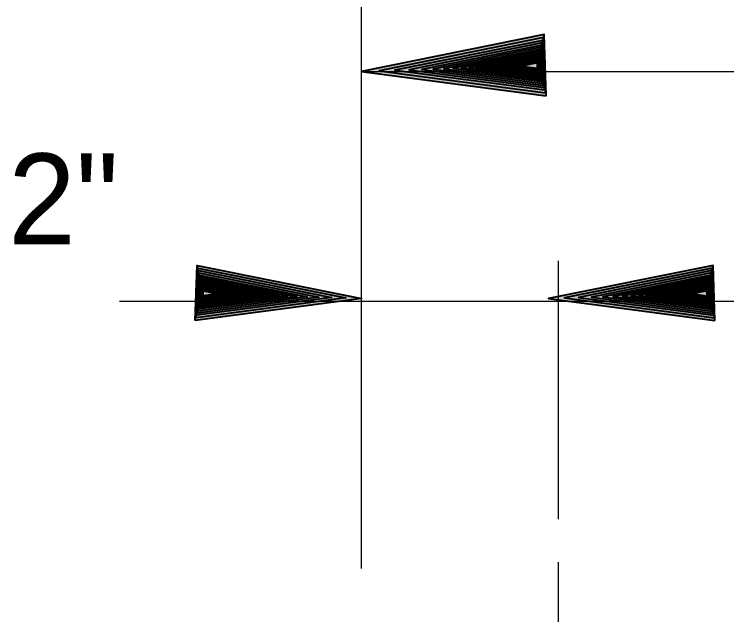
# Model space of a CAD drawing. Extents: x 895.6 to 930.4, y -2278.6 to -2254.7.
# Drawn here: x 914.73 to 915.738, y -2271.009 to -2270.16 of the extents above; entities that cross this region are included whole.
import ezdxf

# ---------------------------------------------------------------- set-up
doc = ezdxf.new("R2010")
doc.units = 0
doc.header["$LTSCALE"] = 0.051
doc.layers.add('1', color=7, linetype='Continuous', lineweight=70)
doc.layers.add('3', color=7, linetype='Continuous', lineweight=40)

msp = doc.modelspace()

# ---------------------------------------------------------------- hatches: boundary and pattern name
at = {"layer": '3'}
for points in [[(915.48275, -2270.27517), (915.47983, -2270.1885), (915.22142, -2270.24067), (915.22142, -2270.24067)], [(915.4815, -2270.27083), (915.47875, -2270.19283), (915.24617, -2270.23983), (915.24617, -2270.23983)], [(915.48025, -2270.26692), (915.47792, -2270.19683), (915.26858, -2270.23917), (915.26858, -2270.23917)], [(915.47925, -2270.2635), (915.47708, -2270.20042), (915.28858, -2270.23842), (915.28858, -2270.23842)], [(915.47833, -2270.2605), (915.47642, -2270.20367), (915.30667, -2270.23783), (915.30667, -2270.23783)], [(915.47725, -2270.25758), (915.47567, -2270.2065), (915.32292, -2270.23733), (915.32292, -2270.23733)], [(915.47658, -2270.255), (915.47508, -2270.20908), (915.33767, -2270.23683), (915.33767, -2270.23683)], [(915.47575, -2270.25283), (915.4745, -2270.21142), (915.35092, -2270.23633), (915.35092, -2270.23633)], [(915.47533, -2270.25083), (915.474, -2270.21342), (915.36267, -2270.23583), (915.36267, -2270.23583)], [(915.47458, -2270.24892), (915.47342, -2270.21517), (915.3735, -2270.2355), (915.3735, -2270.2355)], [(915.47417, -2270.24733), (915.47308, -2270.217), (915.38308, -2270.23525), (915.38308, -2270.23525)], [(915.47367, -2270.24575), (915.47267, -2270.21858), (915.39167, -2270.23483), (915.39167, -2270.23483)], [(915.47325, -2270.24442), (915.47242, -2270.21992), (915.39958, -2270.23467), (915.39958, -2270.23467)], [(915.47267, -2270.24317), (915.47217, -2270.22117), (915.4065, -2270.23442), (915.4065, -2270.23442)], [(915.4725, -2270.24217), (915.47183, -2270.22225), (915.41275, -2270.23425), (915.41275, -2270.23425)], [(915.47208, -2270.24108), (915.47167, -2270.22325), (915.41842, -2270.23392), (915.41842, -2270.23392)], [(915.47192, -2270.24017), (915.47133, -2270.22408), (915.4235, -2270.23375), (915.4235, -2270.23375)], [(915.47175, -2270.23933), (915.47117, -2270.22492), (915.42808, -2270.23358), (915.42808, -2270.23358)], [(915.47133, -2270.23892), (915.47108, -2270.22575), (915.43217, -2270.23358), (915.43217, -2270.23358)], [(915.47117, -2270.23833), (915.47075, -2270.2265), (915.43583, -2270.2335), (915.43583, -2270.2335)], [(915.47083, -2270.23783), (915.47042, -2270.22725), (915.43908, -2270.23367), (915.43908, -2270.23367)], [(915.47083, -2270.23725), (915.47042, -2270.22783), (915.44217, -2270.2335), (915.44217, -2270.2335)], [(915.47067, -2270.23675), (915.47033, -2270.22825), (915.44492, -2270.23325), (915.44492, -2270.23325)], [(915.47042, -2270.23633), (915.47025, -2270.22875), (915.44725, -2270.23333), (915.44725, -2270.23333)], [(914.98608, -2270.59308), (914.98875, -2270.51508), (915.22142, -2270.562), (915.22142, -2270.562)], [(915.72142, -2270.59308), (915.71875, -2270.51508), (915.48608, -2270.562), (915.48608, -2270.562)], [(914.98733, -2270.58917), (914.98967, -2270.519), (915.199, -2270.56117), (915.199, -2270.56117)], [(914.98833, -2270.58567), (914.9905, -2270.52258), (915.17892, -2270.56058), (915.17892, -2270.56058)], [(914.98933, -2270.58258), (914.99125, -2270.52583), (915.16083, -2270.56), (915.16083, -2270.56)], [(915.72017, -2270.58917), (915.71783, -2270.519), (915.5085, -2270.56117), (915.5085, -2270.56117)], [(915.71917, -2270.58567), (915.717, -2270.52258), (915.52858, -2270.56058), (915.52858, -2270.56058)], [(915.71817, -2270.58258), (915.71625, -2270.52583), (915.54667, -2270.56), (915.54667, -2270.56)], [(914.99008, -2270.57992), (914.99192, -2270.52875), (915.14458, -2270.5595), (915.14458, -2270.5595)], [(914.99108, -2270.57725), (914.99258, -2270.53125), (915.12992, -2270.559), (915.12992, -2270.559)], [(914.99167, -2270.57492), (914.993, -2270.5335), (915.11675, -2270.5585), (915.11675, -2270.5585)], [(914.99242, -2270.573), (914.9935, -2270.53567), (915.10475, -2270.55817), (915.10475, -2270.55817)], [(915.71742, -2270.57992), (915.71558, -2270.52875), (915.56292, -2270.5595), (915.56292, -2270.5595)], [(915.71642, -2270.57725), (915.71492, -2270.53125), (915.57758, -2270.559), (915.57758, -2270.559)], [(915.71583, -2270.57492), (915.7145, -2270.5335), (915.59075, -2270.5585), (915.59075, -2270.5585)], [(915.71508, -2270.573), (915.714, -2270.53567), (915.60275, -2270.55817), (915.60275, -2270.55817)], [(914.99275, -2270.57117), (914.99408, -2270.5375), (915.09417, -2270.55767), (915.09417, -2270.55767)], [(914.99342, -2270.56942), (914.9945, -2270.53908), (915.0845, -2270.55742), (915.0845, -2270.55742)], [(914.99392, -2270.56792), (914.99483, -2270.54075), (915.07583, -2270.55708), (915.07583, -2270.55708)], [(914.99425, -2270.5665), (914.99517, -2270.54217), (915.06808, -2270.55675), (915.06808, -2270.55675)], [(914.99475, -2270.56542), (914.99542, -2270.54333), (915.06092, -2270.55658), (915.06092, -2270.55658)], [(914.99517, -2270.56425), (914.99567, -2270.54442), (915.05483, -2270.55642), (915.05483, -2270.55642)], [(914.99542, -2270.56333), (914.996, -2270.54542), (915.04908, -2270.55625), (915.04908, -2270.55625)], [(914.99567, -2270.56242), (914.99608, -2270.54625), (915.044, -2270.55592), (915.044, -2270.55592)], [(915.71475, -2270.57117), (915.71342, -2270.5375), (915.61333, -2270.55767), (915.61333, -2270.55767)], [(915.71408, -2270.56942), (915.713, -2270.53908), (915.623, -2270.55742), (915.623, -2270.55742)], [(915.71358, -2270.56792), (915.71267, -2270.54075), (915.63167, -2270.55708), (915.63167, -2270.55708)], [(915.71325, -2270.5665), (915.71233, -2270.54217), (915.63942, -2270.55675), (915.63942, -2270.55675)], [(915.71275, -2270.56542), (915.71208, -2270.54333), (915.64658, -2270.55658), (915.64658, -2270.55658)], [(915.71233, -2270.56425), (915.71183, -2270.54442), (915.65267, -2270.55642), (915.65267, -2270.55642)], [(915.71208, -2270.56333), (915.7115, -2270.54542), (915.65842, -2270.55625), (915.65842, -2270.55625)], [(915.71183, -2270.56242), (915.71142, -2270.54625), (915.6635, -2270.55592), (915.6635, -2270.55592)], [(914.99592, -2270.56158), (914.99642, -2270.547), (915.03942, -2270.55575), (915.03942, -2270.55575)], [(914.99608, -2270.56083), (914.9965, -2270.54783), (915.03533, -2270.55567), (915.03533, -2270.55567)], [(914.99642, -2270.56042), (914.99667, -2270.54858), (915.03167, -2270.55567), (915.03167, -2270.55567)], [(914.99658, -2270.55983), (914.99692, -2270.54925), (915.02842, -2270.55558), (915.02842, -2270.55558)], [(914.99683, -2270.5595), (914.99717, -2270.54992), (915.02542, -2270.55575), (915.02542, -2270.55575)], [(914.99683, -2270.55892), (914.99717, -2270.55042), (915.02267, -2270.55558), (915.02267, -2270.55558)], [(914.997, -2270.55842), (914.99733, -2270.55083), (915.02025, -2270.55533), (915.02025, -2270.55533)], [(914.99717, -2270.55817), (914.99742, -2270.55133), (915.01808, -2270.55542), (915.01808, -2270.55542)], [(915.71158, -2270.56158), (915.71108, -2270.547), (915.66808, -2270.55575), (915.66808, -2270.55575)], [(915.71142, -2270.56083), (915.711, -2270.54783), (915.67217, -2270.55567), (915.67217, -2270.55567)], [(915.71108, -2270.56042), (915.71083, -2270.54858), (915.67583, -2270.55567), (915.67583, -2270.55567)], [(915.71092, -2270.55983), (915.71058, -2270.54925), (915.67908, -2270.55558), (915.67908, -2270.55558)], [(915.71067, -2270.5595), (915.71033, -2270.54992), (915.68208, -2270.55575), (915.68208, -2270.55575)], [(915.71067, -2270.55892), (915.71033, -2270.55042), (915.68483, -2270.55558), (915.68483, -2270.55558)], [(915.7105, -2270.55842), (915.71017, -2270.55083), (915.68725, -2270.55533), (915.68725, -2270.55533)], [(915.71033, -2270.55817), (915.71008, -2270.55133), (915.68942, -2270.55542), (915.68942, -2270.55542)]]:
    msp.add_hatch(color=256, dxfattribs=at).paths.add_polyline_path(points)

# ---------------------------------------------------------------- linework, layer by layer
at = {"layer": '1', "lineweight": 25}
for p, q in [((915.22142, -2270.94408), (915.22142, -2268.92592)), ((915.22142, -2270.24067), (918.1585, -2270.24067)), ((915.5, -2270.87417), (915.5, -2270.50858)), ((914.87908, -2270.56583), (916.57192, -2270.56583)), ((915.5, -2271.12992), (915.5, -2270.93508))]:
    msp.add_line(p, q, dxfattribs=at)
at = {"layer": '3'}
for points in [[(915.48275, -2270.27517), (915.47983, -2270.1885), (915.22142, -2270.24067), (915.22142, -2270.24067)], [(915.4815, -2270.27083), (915.47875, -2270.19283), (915.24617, -2270.23983), (915.24617, -2270.23983)], [(915.48025, -2270.26692), (915.47792, -2270.19683), (915.26858, -2270.23917), (915.26858, -2270.23917)], [(915.47925, -2270.2635), (915.47708, -2270.20042), (915.28858, -2270.23842), (915.28858, -2270.23842)], [(915.47833, -2270.2605), (915.47642, -2270.20367), (915.30667, -2270.23783), (915.30667, -2270.23783)], [(915.47725, -2270.25758), (915.47567, -2270.2065), (915.32292, -2270.23733), (915.32292, -2270.23733)], [(915.47658, -2270.255), (915.47508, -2270.20908), (915.33767, -2270.23683), (915.33767, -2270.23683)], [(915.47575, -2270.25283), (915.4745, -2270.21142), (915.35092, -2270.23633), (915.35092, -2270.23633)], [(915.47533, -2270.25083), (915.474, -2270.21342), (915.36267, -2270.23583), (915.36267, -2270.23583)], [(915.47458, -2270.24892), (915.47342, -2270.21517), (915.3735, -2270.2355), (915.3735, -2270.2355)], [(915.47417, -2270.24733), (915.47308, -2270.217), (915.38308, -2270.23525), (915.38308, -2270.23525)], [(915.47367, -2270.24575), (915.47267, -2270.21858), (915.39167, -2270.23483), (915.39167, -2270.23483)], [(915.47325, -2270.24442), (915.47242, -2270.21992), (915.39958, -2270.23467), (915.39958, -2270.23467)], [(915.47267, -2270.24317), (915.47217, -2270.22117), (915.4065, -2270.23442), (915.4065, -2270.23442)], [(915.4725, -2270.24217), (915.47183, -2270.22225), (915.41275, -2270.23425), (915.41275, -2270.23425)], [(915.47208, -2270.24108), (915.47167, -2270.22325), (915.41842, -2270.23392), (915.41842, -2270.23392)], [(915.47192, -2270.24017), (915.47133, -2270.22408), (915.4235, -2270.23375), (915.4235, -2270.23375)], [(915.47175, -2270.23933), (915.47117, -2270.22492), (915.42808, -2270.23358), (915.42808, -2270.23358)], [(915.47133, -2270.23892), (915.47108, -2270.22575), (915.43217, -2270.23358), (915.43217, -2270.23358)], [(915.47117, -2270.23833), (915.47075, -2270.2265), (915.43583, -2270.2335), (915.43583, -2270.2335)], [(915.47083, -2270.23783), (915.47042, -2270.22725), (915.43908, -2270.23367), (915.43908, -2270.23367)], [(915.47083, -2270.23725), (915.47042, -2270.22783), (915.44217, -2270.2335), (915.44217, -2270.2335)], [(915.47067, -2270.23675), (915.47033, -2270.22825), (915.44492, -2270.23325), (915.44492, -2270.23325)], [(915.47042, -2270.23633), (915.47025, -2270.22875), (915.44725, -2270.23333), (915.44725, -2270.23333)], [(914.98608, -2270.59308), (914.98875, -2270.51508), (915.22142, -2270.562), (915.22142, -2270.562)], [(915.72142, -2270.59308), (915.71875, -2270.51508), (915.48608, -2270.562), (915.48608, -2270.562)], [(914.98733, -2270.58917), (914.98967, -2270.519), (915.199, -2270.56117), (915.199, -2270.56117)], [(914.98833, -2270.58567), (914.9905, -2270.52258), (915.17892, -2270.56058), (915.17892, -2270.56058)], [(914.98933, -2270.58258), (914.99125, -2270.52583), (915.16083, -2270.56), (915.16083, -2270.56)], [(915.72017, -2270.58917), (915.71783, -2270.519), (915.5085, -2270.56117), (915.5085, -2270.56117)], [(915.71917, -2270.58567), (915.717, -2270.52258), (915.52858, -2270.56058), (915.52858, -2270.56058)], [(915.71817, -2270.58258), (915.71625, -2270.52583), (915.54667, -2270.56), (915.54667, -2270.56)], [(914.99008, -2270.57992), (914.99192, -2270.52875), (915.14458, -2270.5595), (915.14458, -2270.5595)], [(914.99108, -2270.57725), (914.99258, -2270.53125), (915.12992, -2270.559), (915.12992, -2270.559)], [(914.99167, -2270.57492), (914.993, -2270.5335), (915.11675, -2270.5585), (915.11675, -2270.5585)], [(914.99242, -2270.573), (914.9935, -2270.53567), (915.10475, -2270.55817), (915.10475, -2270.55817)], [(915.71742, -2270.57992), (915.71558, -2270.52875), (915.56292, -2270.5595), (915.56292, -2270.5595)], [(915.71642, -2270.57725), (915.71492, -2270.53125), (915.57758, -2270.559), (915.57758, -2270.559)], [(915.71583, -2270.57492), (915.7145, -2270.5335), (915.59075, -2270.5585), (915.59075, -2270.5585)], [(915.71508, -2270.573), (915.714, -2270.53567), (915.60275, -2270.55817), (915.60275, -2270.55817)], [(914.99275, -2270.57117), (914.99408, -2270.5375), (915.09417, -2270.55767), (915.09417, -2270.55767)], [(914.99342, -2270.56942), (914.9945, -2270.53908), (915.0845, -2270.55742), (915.0845, -2270.55742)], [(914.99392, -2270.56792), (914.99483, -2270.54075), (915.07583, -2270.55708), (915.07583, -2270.55708)], [(914.99425, -2270.5665), (914.99517, -2270.54217), (915.06808, -2270.55675), (915.06808, -2270.55675)], [(914.99475, -2270.56542), (914.99542, -2270.54333), (915.06092, -2270.55658), (915.06092, -2270.55658)], [(914.99517, -2270.56425), (914.99567, -2270.54442), (915.05483, -2270.55642), (915.05483, -2270.55642)], [(914.99542, -2270.56333), (914.996, -2270.54542), (915.04908, -2270.55625), (915.04908, -2270.55625)], [(914.99567, -2270.56242), (914.99608, -2270.54625), (915.044, -2270.55592), (915.044, -2270.55592)], [(915.71475, -2270.57117), (915.71342, -2270.5375), (915.61333, -2270.55767), (915.61333, -2270.55767)], [(915.71408, -2270.56942), (915.713, -2270.53908), (915.623, -2270.55742), (915.623, -2270.55742)], [(915.71358, -2270.56792), (915.71267, -2270.54075), (915.63167, -2270.55708), (915.63167, -2270.55708)], [(915.71325, -2270.5665), (915.71233, -2270.54217), (915.63942, -2270.55675), (915.63942, -2270.55675)], [(915.71275, -2270.56542), (915.71208, -2270.54333), (915.64658, -2270.55658), (915.64658, -2270.55658)], [(915.71233, -2270.56425), (915.71183, -2270.54442), (915.65267, -2270.55642), (915.65267, -2270.55642)], [(915.71208, -2270.56333), (915.7115, -2270.54542), (915.65842, -2270.55625), (915.65842, -2270.55625)], [(915.71183, -2270.56242), (915.71142, -2270.54625), (915.6635, -2270.55592), (915.6635, -2270.55592)], [(914.99592, -2270.56158), (914.99642, -2270.547), (915.03942, -2270.55575), (915.03942, -2270.55575)], [(914.99608, -2270.56083), (914.9965, -2270.54783), (915.03533, -2270.55567), (915.03533, -2270.55567)], [(914.99642, -2270.56042), (914.99667, -2270.54858), (915.03167, -2270.55567), (915.03167, -2270.55567)], [(914.99658, -2270.55983), (914.99692, -2270.54925), (915.02842, -2270.55558), (915.02842, -2270.55558)], [(914.99683, -2270.5595), (914.99717, -2270.54992), (915.02542, -2270.55575), (915.02542, -2270.55575)], [(914.99683, -2270.55892), (914.99717, -2270.55042), (915.02267, -2270.55558), (915.02267, -2270.55558)], [(914.997, -2270.55842), (914.99733, -2270.55083), (915.02025, -2270.55533), (915.02025, -2270.55533)], [(914.99717, -2270.55817), (914.99742, -2270.55133), (915.01808, -2270.55542), (915.01808, -2270.55542)], [(915.71158, -2270.56158), (915.71108, -2270.547), (915.66808, -2270.55575), (915.66808, -2270.55575)], [(915.71142, -2270.56083), (915.711, -2270.54783), (915.67217, -2270.55567), (915.67217, -2270.55567)], [(915.71108, -2270.56042), (915.71083, -2270.54858), (915.67583, -2270.55567), (915.67583, -2270.55567)], [(915.71092, -2270.55983), (915.71058, -2270.54925), (915.67908, -2270.55558), (915.67908, -2270.55558)], [(915.71067, -2270.5595), (915.71033, -2270.54992), (915.68208, -2270.55575), (915.68208, -2270.55575)], [(915.71067, -2270.55892), (915.71033, -2270.55042), (915.68483, -2270.55558), (915.68483, -2270.55558)], [(915.7105, -2270.55842), (915.71017, -2270.55083), (915.68725, -2270.55533), (915.68725, -2270.55533)], [(915.71033, -2270.55817), (915.71008, -2270.55133), (915.68942, -2270.55542), (915.68942, -2270.55542)]]:
    msp.add_lwpolyline(points, close=True, dxfattribs=at)

# ---------------------------------------------------------------- texts
at = {"layer": '1'}
msp.add_text('2"', height=0.1286, dxfattribs=at).set_placement((914.72133, -2270.48542))

doc.saveas('drawing.dxf')
